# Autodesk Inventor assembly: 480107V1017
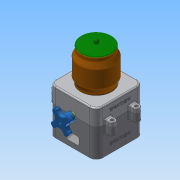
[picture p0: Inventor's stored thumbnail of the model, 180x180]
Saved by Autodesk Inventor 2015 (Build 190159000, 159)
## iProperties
Created: 2018-01
Part Number: 480107V1017
Document SubType Name: Assembly
Designer: user
Author: user
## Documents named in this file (7)
- C:\Users\user\Desktop\480107V1017\480107V1017.iam
- C:\Users\user\Desktop\480107V1017\본체.ipt
- C:\Users\user\Desktop\480107V1017\핸들축.ipt
- C:\Users\user\Desktop\480107V1017\본체커버.ipt
- C:\Users\user\Desktop\480107V1017\용기.ipt
- C:\Users\user\Desktop\480107V1017\용기캡.ipt
- C:\Users\user\Desktop\480107V1017\핸들.ipt
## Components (2 placed, 2 different names)
1. 핸들축:1
2. 핸들:1
